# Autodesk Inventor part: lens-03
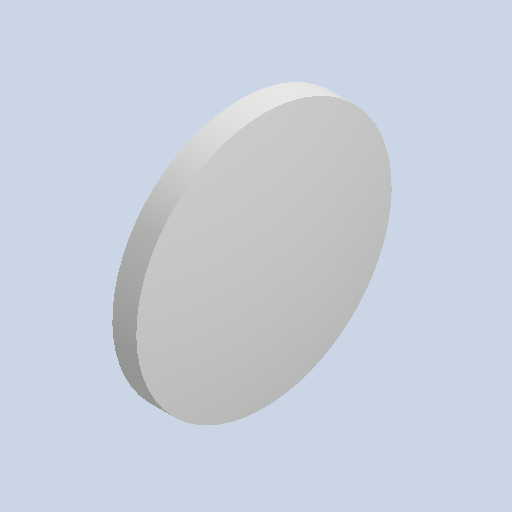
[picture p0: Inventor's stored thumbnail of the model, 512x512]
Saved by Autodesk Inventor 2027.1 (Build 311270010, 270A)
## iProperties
Created: 2026-07
Part Number: lens-03
Material: Generic
Document SubType Name: Modeling
Designer: dunge
Density: 1 g/cm^3
Appearance: Default
Author: dunge
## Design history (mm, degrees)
derived "lens.ipt"
feature "Lens::lens.ipt"
tag "TaggingFeature1"
node "Finishes"
node "Lens"
node "Finish1" dims "Finish1_Area" = 310.61168
other parameters: "SIDE_2_MINOR" = 1.27, "LENS_RADIUS" = 20.32, "SIDE_1_MINOR" = 2.54, "SIDE_1_MAJOR" = 5.08, "SIDE_2_MAJOR" = 2.54
